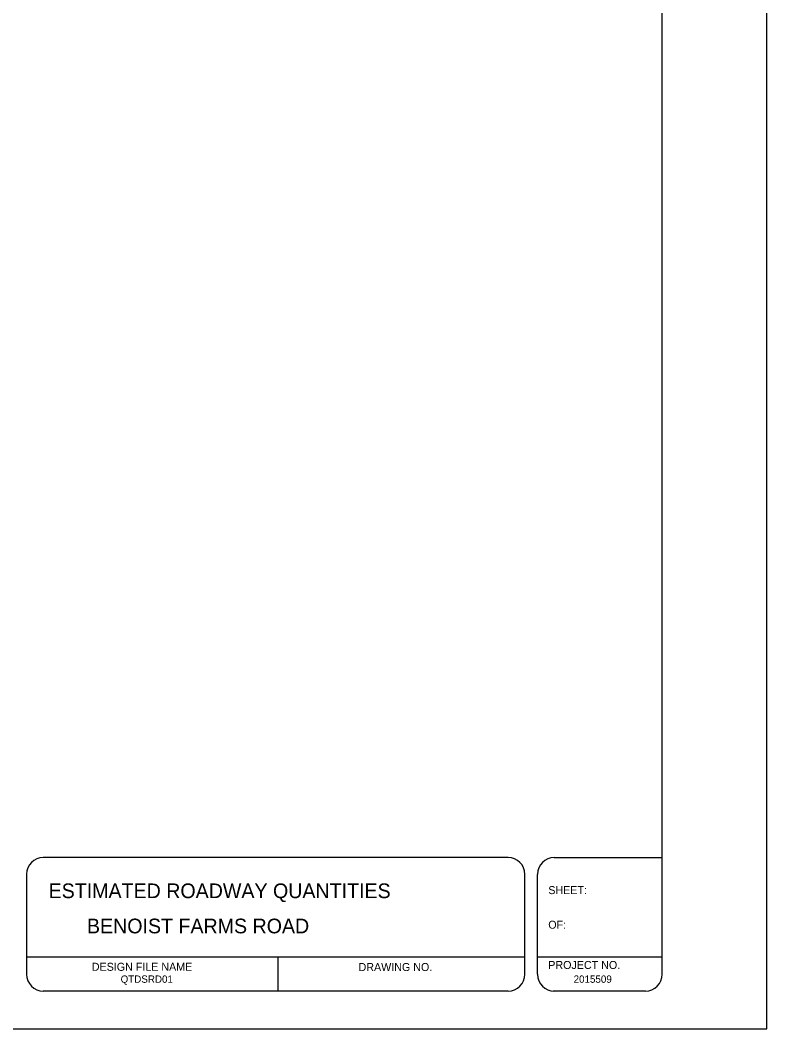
# Model space of a CAD drawing. Extents: x -0.7 to 16, y -0.9 to 9.7.
# Drawn here: x 12.02 to 15.95, y -0.9 to 4.4 of the extents above; entities that cross this region are included whole.
import ezdxf

# ---------------------------------------------------------------- set-up
doc = ezdxf.new("R2010")
doc.units = 0
doc.layers.add('Default', color=7, linetype='Continuous')
doc.layers.add('PlotBorder_dp', color=7, linetype='Continuous')

msp = doc.modelspace()

# ---------------------------------------------------------------- linework, layer by layer
at = {"layer": 'Default'}
for p, q in [((15.4, -0.6133), (15.4, 9.5065)), ((14.5898, 0), (12.146, 0)), ((14.8324, 0), (15.4, 0)), ((12.0578, -0.0882), (12.0578, -0.6131)), ((14.678, -0.6135), (14.678, -0.0884)), ((14.7442, -0.6135), (14.7442, -0.0884)), ((14.6769, -0.5241), (12.0568, -0.5241)), ((13.3801, -0.7005), (13.3801, -0.5241)), ((15.4, -0.5241), (14.7475, -0.5241)), ((14.5898, -0.7014), (12.146, -0.7014)), ((15.3118, -0.7015), (14.8271, -0.7015))]:
    msp.add_line(p, q, dxfattribs=at)
for centre, major_axis, start_param, end_param in [((12.146, -0.0882), (0, 0.0882), 0, 1.570796), ((14.5898, -0.0884), (0, 0.0882), 4.712389, 6.283185), ((14.8324, -0.0884), (0, -0.0882), 3.141593, 4.712389), ((12.146, -0.6131), (0, -0.0882), 4.712389, 6.283185), ((14.5898, -0.6131), (0, 0.0882), 3.141593, 4.712389), ((14.8324, -0.6135), (0, -0.0882), 4.712389, 6.283185), ((15.3118, -0.6133), (0, -0.0882), 0, 1.570796)]:
    msp.add_ellipse(centre, major_axis=major_axis, ratio=0.999927, start_param=start_param, end_param=end_param, dxfattribs=at)
at = {"layer": 'PlotBorder_dp'}
msp.add_lwpolyline([(-0.55, -0.9), (15.95, -0.9), (15.95, 9.7), (-0.55, 9.7)], close=True, dxfattribs=at)

# ---------------------------------------------------------------- texts
at = {"layer": 'Default'}
for s, height, p in [('ESTIMATED ROADWAY QUANTITIES', 0.077091, (12.1737, -0.2133)), ('SHEET:', 0.04207, (14.8009, -0.1922)), ('   BENOIST FARMS ROAD   ', 0.077091, (12.2895, -0.3982)), ('OF:', 0.04207, (14.8009, -0.374)), ('DESIGN FILE NAME', 0.042066, (12.4009, -0.5951)), ('DRAWING NO.', 0.042066, (13.8035, -0.5964)), ('PROJECT NO.', 0.042066, (14.8009, -0.5856)), ('QTDSRD01', 0.03855, (12.5524, -0.6581)), ('2015509', 0.03855, (14.9341, -0.6581))]:
    msp.add_text(s, height=height, dxfattribs=at).set_placement(p)

doc.saveas('drawing.dxf')
